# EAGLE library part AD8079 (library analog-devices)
Dual 260 MHz Gain = +2.0 & +2.2 Buffer Source: http://www.analog.com/static/imported-files/data_sheets/AD8079.pdf
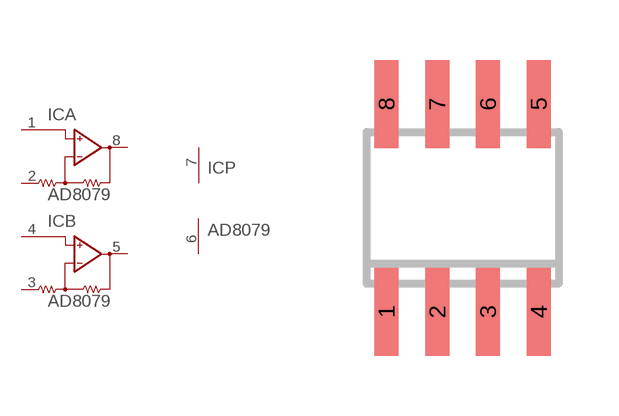
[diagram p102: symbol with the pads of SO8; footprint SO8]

Designator prefix IC; gates A=OP-GAIN B=OP-GAIN P=PWR+-

## AD8079 (MF: ALTERA CORPORATION; MPN: AD8079BRZ; OC_FARNELL: 1838858; OC_NEWARK: 59K6340)  [SO8]
1  A:IN+  in
2  A:GND  pas
3  B:GND  pas
4  B:IN+  in
5  B:OUT  out
6  P:V-  pwr
7  P:V+  pwr
8  A:OUT  out

## Footprint SO8 (pad centres in mm)
8-Lead Small Outline IC (SO-8) Source: http://www.analog.com/UploadedFiles/Data_Sheets/703465986AD8611_2_0.pdf
smd 0.6 x 2.2: 1 -1.905,-2.6; 2 -0.635,-2.6; 3 0.635,-2.6; 4 1.905,-2.6; 5 1.905,2.6; 6 0.635,2.6; 7 -0.635,2.6; 8 -1.905,2.6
